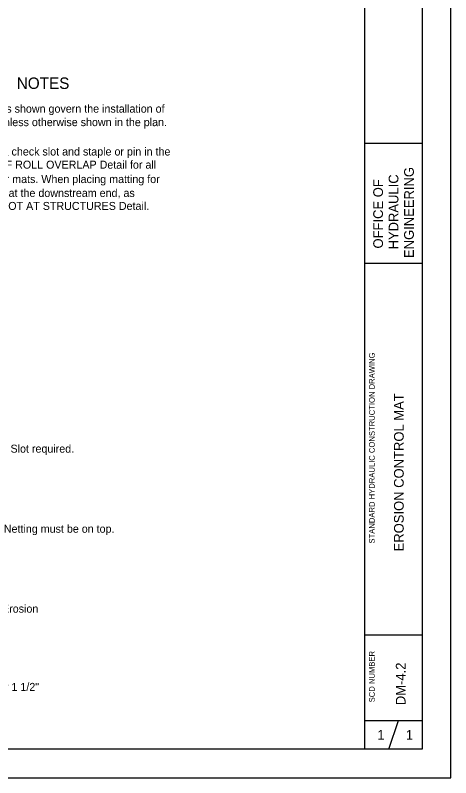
# Model space of a CAD drawing. Extents: x 1083.1 to 1117.1, y 719.4 to 741.4.
# Drawn here: x 1109.51 to 1117.13, y 719.35 to 732.69 of the extents above; entities that cross this region are included whole.
import ezdxf

# ---------------------------------------------------------------- set-up
doc = ezdxf.new("R2010")
doc.units = 0
for name, color, linetype in [('SH_Border', 7, 'Continuous'), ('SH_Cut_Line', 7, 'Continuous'), ('SH_Data', 7, 'Continuous'), ('ST_Text', 7, 'Continuous')]:
    doc.layers.add(name, color=color, linetype=linetype)

msp = doc.modelspace()

# ---------------------------------------------------------------- linework, layer by layer
at = {"layer": 'SH_Border'}
for p, q in [((1115.626, 719.854), (1115.626, 740.854)), ((1115.626, 730.454), (1116.626, 730.454)), ((1115.626, 728.354), (1116.626, 728.354)), ((1115.626, 721.854), (1116.626, 721.854)), ((1115.626, 720.354), (1116.626, 720.354)), ((1116.043, 719.854), (1116.21, 720.354))]:
    msp.add_line(p, q, dxfattribs=at)
msp.add_lwpolyline([(1085.126, 740.854), (1116.626, 740.854), (1116.626, 719.854), (1085.126, 719.854)], close=True, dxfattribs=at)
at = {"layer": 'SH_Cut_Line'}
msp.add_lwpolyline([(1083.126, 719.354), (1117.126, 719.354), (1117.126, 741.354), (1083.126, 741.354)], close=True, dxfattribs=at)

# ---------------------------------------------------------------- texts
at = {"layer": 'SH_Data'}
for s, height, p in [('HYDRAULIC', 0.17, (1116.211, 728.596)), ('ENGINEERING', 0.17, (1116.481, 728.446)), ('OFFICE OF', 0.17, (1115.941, 728.612)), ('STANDARD HYDRAULIC CONSTRUCTION DRAWING', 0.1, (1115.797, 723.451)), ('EROSION CONTROL MAT', 0.17, (1116.304, 723.314)), ('SCD NUMBER', 0.1, (1115.797, 720.673)), ('DM-4.2', 0.17, (1116.336, 720.624))]:
    msp.add_text(s, height=height, rotation=90, dxfattribs=at).set_placement(p)
for p in [(1115.841, 720.019), (1116.341, 720.019)]:
    msp.add_text('1', height=0.17, dxfattribs=at).set_placement(p)
at = {"layer": 'ST_Text'}
for s, height, p in [('NOTES', 0.2, (1109.535, 731.404)), ('The details shown govern the installation of', 0.14, (1108.53, 730.989)), ('Erosion Control Mats unless otherwise shown in the plan.', 0.14, (1107.407, 730.753)), ('Use a check slot and staple or pin in the', 0.14, (1108.903, 730.239)), ('slot as shown in END OF ROLL OVERLAP Detail for all', 0.14, (1107.364, 730.009)), ('mats excluding excelsior mats. When placing matting for', 0.14, (1107.364, 729.757)), ('all ditch protection, start at the downstream end, as ', 0.14, (1107.364, 729.514)), ('shown in the CHECK SLOT AT STRUCTURES Detail.', 0.14, (1107.347, 729.287)), ('End Slot required.', 0.14, (1109.041, 725.041)), ('Netting must be on top.', 0.14, (1109.309, 723.64)), ('Excelsior Erosion', 0.14, (1108.466, 722.242)), ('Overlap upgrade mat by 1 1/2"', 0.14, (1107.382, 720.873))]:
    msp.add_text(s, height=height, dxfattribs=at).set_placement(p)

doc.saveas('drawing.dxf')
